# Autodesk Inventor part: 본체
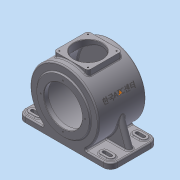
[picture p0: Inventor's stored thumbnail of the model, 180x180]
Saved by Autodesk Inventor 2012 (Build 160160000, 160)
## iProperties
Created: 2015-06
Part Number: 본체
Material: 알루미늄-6061
Document SubType Name: Modeling
Designer: Administrator
Density: 2.71 g/cm^3
Mass: 3275.31 g
Surface Area: 2299.71 cm^2
Volume: 1208.6 cm^3
Author: Administrator
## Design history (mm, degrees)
sketch "스케치1"
  geometry: C1 r 85 at (0, 0); 1 further point
  constraints: 1 centre point, 1 coincident
  dimensions: "d0" = 170 diameter of C1
extrude "돌출1" new body sketch "스케치1" stored distance "d1" = 118; taper "d2" = 0 deg
sketch "스케치3"
  geometry: L1 (-115, -85)-(115, -85); L2 (115, -85)-(115, -71); L3 (115, -71)-(-115, -71); L4 (-115, -71)-(-115, -85); 2 further points
  constraints: 8 end point, 2 parallel, 1 horizontal, 1 midpoint, 1 perpendicular, 1 vertical alignment
  dimensions: "d6" = 230 distance of L3.end L2.end; "d7" = 14 distance of L2.end L1.end; "d8" = 85 distance from line of L1 point (0, 0)
extrude "돌출2" join sketch "스케치3" stored distance "d9" = 118; taper "d10" = 0 deg
sketch "스케치4"
  geometry: L1 (72.5, -101.5)-(157.5, -101.5); L2 (157.5, -101.5)-(157.5, -16.5); L3 (157.5, -16.5)-(72.5, -16.5); L4 (72.5, -16.5)-(72.5, -101.5); 3 further points
  constraints: 8 end point, 2 midpoint, 2 parallel, 1 horizontal, 1 horizontal alignment, 1 perpendicular, 1 vertical alignment
  dimensions: "d11" = 85 distance of L3.end L2.end; "d12" = 85 distance of L2.end L1.end
extrude "돌출3" join sketch "스케치4" distance "d13" = 173; taper "d14" = 0 deg
sketch "스케치2"
  geometry: L1 (-51, 0)-(51, 0); L2 (51, 0)-(51, 77); L3 (51, 77)-(-51, 77); L4 (-51, 77)-(-51, 0); L5 (-59, 85)-(59, 85) reference; 2 further points
  constraints: 8 end point, 2 parallel, 1 coincident, 1 horizontal, 1 midpoint, 1 perpendicular
  dimensions: "d3" = 102 distance of L2.end L3.end; "d4" = 8 distance between parallel lines of L3 L5
revolve "회전1" sketch "스케치2" stored, may be unused: angle "d5" = 90 deg
sketch "스케치5"
  geometry: C1 r 65 at (0, 0); A1 r 85 centre (0, 0) between (46.733, -71) and (-46.733, -71) reference
  constraints: 1 centre point, 1 coincident
  dimensions: "d15" = 130 diameter of C1
extrude "돌출4" join sketch "스케치5" distance "d16" = 3; taper "d17" = 0 deg
sketch "스케치6"
  geometry: C1 r 65 at (0, 0); A1 r 85 centre (0, 0) between (-46.733, 71) and (46.733, 71) reference
  constraints: 1 centre point, 1 coincident
  dimensions: "d18" = 130 diameter of C1
extrude "돌출5" join sketch "스케치6" distance "d19" = 13; taper "d20" = 0 deg
hole "구멍1" diameter "d23" = 95; stored, may be unused: countersink angle "d27" = 90 deg, drill point angle "d29" = 118 deg; dims "d21" = 10, "d22" = 10, "d24" = 6, "d25" = 4, "d26" = 2, "d28" = 8
sketch "스케치7"
  geometry: C1 r 77 at (0, 0) reference; C2 r 31 at (0, 0)
  constraints: 1 centre point, 1 coincident
  dimensions: "d30" = 62 diameter of C2
extrude "돌출6" join sketch "스케치7" distance "d31" = 3.5; taper "d32" = -25 deg
hole "구멍2" diameter "d35" = 30; stored, may be unused: countersink angle "d39" = 90 deg, drill point angle "d41" = 0 deg; dims "d33" = 10, "d34" = 10, "d36" = 6, "d37" = 47, "d38" = 14, "d40" = 17
sketch "스케치8"
  geometry: 1 further point
hole "구멍3" sketch "스케치8" at (-115, -59) diameter "d42" = 70; stored, may be unused: countersink angle "d46" = 90 deg, drill point angle "d48" = 0 deg; dims "d43" = 6, "d44" = 47, "d45" = 14, "d47" = 17
fillet "모깎기8" dims "d97" = 3
fillet "모깎기1" dims "d49" = 3, "d50" = 0.3
fillet "모깎기9" dims "d98" = 18
chamfer "모따기1" distance "d51" = 1; stored, may be unused: second distance "d52" = 2, angle "d53" = 45 deg
fillet "모깎기2" dims "d54" = 3
fillet "모깎기4" dims "d56" = 7
fillet "모깎기5" dims "d57" = 3
sketch "스케치9"
  geometry: C1 r 36 at (-115, -59) reference; 1 further point
  dimensions: "d58" = 35.5 horizontal distance of C1.centre point (-150.5, -23.5); "d59" = 35.5 horizontal distance of C1.centre point (-150.5, -23.5)
hole "구멍4" sketch "스케치9" at (-150.5, -23.5) diameter "d60" = 3.242; stored, may be unused: countersink angle "d64" = 90 deg, drill point angle "d66" = 118 deg; dims "d61" = 10, "d62" = 47, "d63" = 14, "d65" = 13
sketch "스케치10"
  geometry: C1 r 65 at (0, 0) reference; 1 further point
  constraints: 1 vertical alignment
  dimensions: "d70" = 55 distance of C1.centre point (0, 55)
hole "구멍5" sketch "스케치10" at (0, 55) diameter "d71" = 3.242; stored, may be unused: countersink angle "d75" = 90 deg, drill point angle "d77" = 118 deg; dims "d72" = 30, "d73" = 47, "d74" = 14, "d76" = 13
sketch "스케치14"
  geometry: L1 (25.143, 88)-(41.143, 88); L2 (41.143, 88)-(41.143, 106); L3 (41.143, 106)-(25.143, 106); L4 (25.143, 106)-(25.143, 88); A1 r 9 centre (41.143, 97) between (41.143, 88) and (41.143, 106); A2 r 9 centre (25.143, 97) between (25.143, 106) and (25.143, 88); A3 r 18 centre (41.143, 97) between (59.143, 97) and (41.143, 115) reference; 1 further point
  constraints: 8 end point, 4 point on circle, 2 centre point, 2 midpoint, 2 parallel, 1 concentric, 1 horizontal, 1 perpendicular
  dimensions: "d101" = 16 distance of L3.end L2.end; "d102" = 18 distance of L2.end L1.end
extrude "돌출9" join sketch "스케치14" distance "d103" = 3; taper "d104" = 0 deg
sketch "스케치15"
  geometry: L1 (41.143, 88)-(25.143, 88) reference; L2 (25.143, 106)-(41.143, 106) reference; L3 (41.143, 93)-(25.143, 93); L4 (25.143, 101)-(41.143, 101); A1 r 9 centre (25.143, 97) between (25.143, 106) and (25.143, 88) reference; A2 r 9 centre (41.143, 97) between (41.143, 88) and (41.143, 106) reference; A3 r 4 centre (41.143, 97) between (41.143, 93) and (41.143, 101); A4 r 4 centre (25.143, 97) between (25.143, 101) and (25.143, 93); 1 further point
  constraints: 4 end point, 4 point on circle, 2 centre point, 3 other
  dimensions: "d105" = 4 radius of A3
extrude "돌출10" cut sketch "스케치15" stored distance "d106" = 3; taper "d107" = 0 deg
fillet "모깎기10" dims "d108" = 3
sketch "스케치16"
  geometry: L1 (-84.87, -4.703)-(-109, -71); L2 (-115, -85)-(-115, -74) reference; L3 (-112, -71)-(-97, -71) reference; A1 r 85 centre (0, 0) between (53.953, -65.682) and (-53.953, -65.682) reference; 1 further point
  constraints: 2 end point, 1 point on circle, 1 point on line
  dimensions: "d111" = 6 distance from line of L1.end L2; "d112" = 110 deg angle of L3 L1
feature "리브2" sketch "스케치16" dims "d113" = 1, "d114" = 15, "d115" = 0, "d116" = 0, "d117" = 1, "d118" = 1
fillet "모깎기11"
fillet "모깎기12" dims "d119" = 3
sketch "스케치17"
  geometry: L1 (-106.598, 0)-(0, 0); L2 (0, 0)-(-107.184, 49.981)
  constraints: 4 end point, 1 horizontal
  dimensions: "d120" = 25 deg angle of L1 L2
node "작업 평면1"
  node "작업점1"
sketch "스케치18"
  geometry: L1 (-40, 5)-(40, 5); L2 (40, 5)-(40, -5); L3 (40, -5)-(-40, -5); L4 (-40, -5)-(-40, 5); L5 (0, 5)-(0, -5); 2 further points
  constraints: 3 midpoint, 2 end point, 1 coincident, 1 vertical, 2 other
  dimensions: "d121" = 80 distance of L1.start L1.end; "d122" = 10 distance of L1.end L2.end
feature "엠보싱1" sketch "스케치18" dims "d0" = 170, "d123" = 0.5, "d124" = 0
node "솔리드1"
pattern_circular "원형 패턴1" dims angle "d68" = 360 deg
pattern_circular "원형 패턴2" dims angle "d79" = 360 deg
mirror "대칭3"
mirror "대칭4"
mirror "대칭5"
